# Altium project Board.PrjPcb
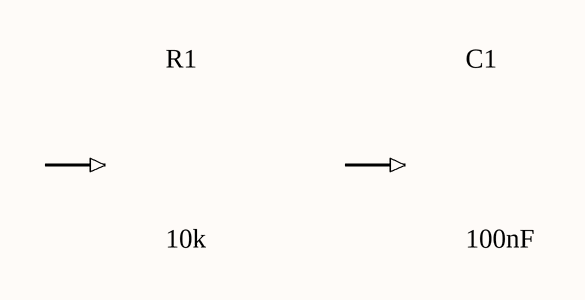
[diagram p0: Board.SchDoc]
1 sheet, 2 parts. Net scope: global (net labels, ports and power ports of the same name join across sheets).
Board file: Board.PcbDoc

## Sheet Board.SchDoc
size A4

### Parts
C1  100nF  [C0402]
R1  10k  [R0603]

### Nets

Not connected (* = marked no-connect by the designer): C1 1; R1 1

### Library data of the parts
C1 = Part1
R1 = Part0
